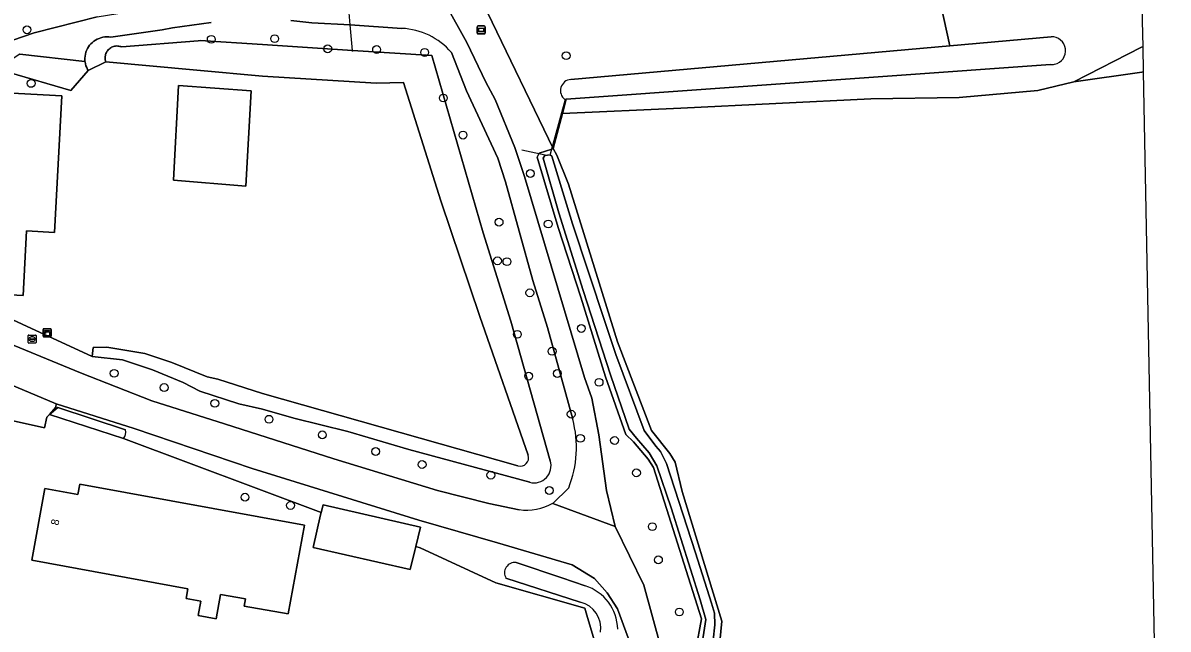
# Model space of a CAD drawing. Extents: x 163859 to 164644, y 379566 to 382155.
# Drawn here: x 164470.1 to 164613.1, y 381262.4 to 381338.2 of the extents above; entities that cross this region are included whole.
import ezdxf

# ---------------------------------------------------------------- set-up
doc = ezdxf.new("R2010")
doc.units = 0
for name, color, linetype in [('IMGEO_Boom', 7, 'Continuous'), ('IMGEO_Duiker', 7, 'Continuous'), ('IMGEO_Erf', 7, 'Continuous'), ('IMGEO_Grasland_agrarisch', 7, 'Continuous'), ('IMGEO_Grasland_overig', 7, 'Continuous'), ('IMGEO_Groenvoorziening', 7, 'Continuous'), ('IMGEO_Houtwal', 7, 'Continuous'), ('IMGEO_Kast', 7, 'Continuous'), ('IMGEO_Oever', 7, 'Continuous'), ('IMGEO_Pand', 7, 'Continuous'), ('IMGEO_Pand_nummerreeks', 7, 'Continuous'), ('IMGEO_Rijbaan_lokaal_onverhard', 7, 'Continuous'), ('IMGEO_Rijbaan_lokaal_open', 7, 'Continuous'), ('IMGEO_Rioolput', 7, 'Continuous'), ('IMGEO_Sloot', 7, 'Continuous'), ('IMGEO_Verklikker', 7, 'Continuous'), ('IMGEO_Waterloop', 7, 'Continuous')]:
    doc.layers.add(name, color=color, linetype=linetype)

msp = doc.modelspace()

# ---------------------------------------------------------------- linework, layer by layer
at = {"layer": 'IMGEO_Boom'}
for centre in [(164470.56, 381337.3), (164493.58, 381336.1), (164501.5, 381336.19), (164508.13, 381334.92), (164514.23, 381334.83), (164520.24, 381334.47), (164537.91, 381334.06), (164471.08, 381330.6), (164522.56, 381328.77), (164525.03, 381324.14), (164533.43, 381319.34), (164529.53, 381313.26), (164535.67, 381313.03), (164529.33, 381308.42), (164530.51, 381308.33), (164533.37, 381304.43), (164539.8, 381299.98), (164531.81, 381299.24), (164536.15, 381297.13), (164481.45, 381294.37), (164533.23, 381294.02), (164536.8, 381294.35), (164487.7, 381292.59), (164542.02, 381293.24), (164494.03, 381290.62), (164500.8, 381288.63), (164538.54, 381289.27), (164507.46, 381286.68), (164539.69, 381286.24), (164543.95, 381285.98), (164514.11, 381284.6), (164519.92, 381282.97), (164528.5, 381281.65), (164546.69, 381281.93), (164535.8, 381279.73), (164497.8, 381278.89), (164503.48, 381277.86), (164548.67, 381275.21), (164549.43, 381271.06), (164552.05, 381264.55)]:
    msp.add_circle(centre, 0.489, dxfattribs=at)
at = {"layer": 'IMGEO_Duiker'}
for points in [[(164511.24, 381334.6), (164511.23, 381334.72), (164510.95, 381337.93), (164510.59, 381341.96), (164510.51, 381342.79), (164510.45, 381343.54), (164510.38, 381344.3)], [(164535.97, 381321.79), (164537.82, 381328.65)], [(164535.29, 381321.62), (164532.37, 381322.25)]]:
    msp.add_lwpolyline(points, dxfattribs=at)
at = {"layer": 'IMGEO_Erf'}
for points in [[(164533.16, 381284.14), (164527.11, 381301.46), (164522.24, 381315.93), (164517.58, 381330.72), (164514.17, 381330.64), (164500, 381331.52), (164491.77, 381332.26), (164480.42, 381333.29), (164478.19, 381332.23), (164476.06, 381329.71), (164468.34, 381331.96)], [(164462.53, 381329.73), (164474.92, 381329.06), (164473.99, 381311.97), (164470.51, 381312.16), (164470.07, 381304.08), (164461.17, 381304.57), (164478.7, 381296.48), (164478.84, 381297.61), (164480.52, 381297.66), (164485.3, 381296.85), (164488.67, 381295.71), (164493.06, 381293.94), (164494.41, 381293.63), (164500, 381291.84), (164531.88, 381282.81)], [(164540.48, 381264.15), (164540.22, 381265.04), (164529.13, 381268.21), (164519.66, 381272.56), (164519.13, 381272.75), (164519.01, 381272.24), (164518.44, 381269.85), (164506.29, 381272.62), (164507.24, 381276.67), (164507.32, 381276.99), (164482.61, 381286.22), (164473.39, 381289.21), (164473.36, 381289.22), (164473.05, 381288.89), (164472.77, 381287.54), (164467.73, 381288.69), (164467.97, 381290.2), (164467.94, 381291.26), (164465.61, 381292.14), (164452.98, 381297.38), (164446.5, 381299.3), (164441.21, 381300.01)], [(164466.17, 381201.68), (164476.78, 381197.2), (164491.42, 381190.96), (164495.42, 381189.33), (164510.56, 381183.16), (164532.99, 381173.22), (164546.62, 381166.36), (164547, 381170.23), (164549.74, 381175.85), (164563.17, 381203.39), (164563.87, 381204.82), (164557.87, 381208.62), (164557.76, 381208.98), (164555.31, 381209.02), (164551.74, 381210.06), (164552.9, 381214.15), (164556.3, 381213.51), (164555.39, 381215.78), (164555.19, 381216.36), (164547.24, 381240.23), (164545.64, 381243.44), (164546.57, 381243.66), (164544.69, 381250), (164540.48, 381264.15)]]:
    msp.add_lwpolyline(points, dxfattribs=at)
for points in [[(164497.92, 381317.77), (164488.86, 381318.51), (164489.5, 381330.35), (164498.57, 381329.66)], [(164491.96, 381264.09), (164492.29, 381265.89), (164490.43, 381266.23), (164490.66, 381267.46), (164471.17, 381271.03), (164472.81, 381279.98), (164476.92, 381279.23), (164477.16, 381280.54), (164505.21, 381275.41), (164503.18, 381264.31), (164497.68, 381265.27), (164497.85, 381266.18), (164494.75, 381266.75), (164494.19, 381263.68)]]:
    msp.add_lwpolyline(points, close=True, dxfattribs=at)
msp.add_arc((164532.17, 381283.81), 1.04, 254.0114, 18.1006, dxfattribs=at)
at = {"layer": 'IMGEO_Grasland_agrarisch'}
msp.add_lwpolyline([(164611.6, 381250), (164610.02, 381332.03), (164609.81, 381332), (164601.31, 381330.81), (164596.82, 381329.72), (164586.98, 381328.83), (164575.98, 381328.66), (164552.22, 381327.5), (164537.45, 381326.82), (164536.3, 381322.47), (164536.75, 381321.62), (164538.21, 381318.01), (164544.33, 381298.3), (164548.58, 381287.22), (164550.85, 381284.34), (164551.54, 381283.27), (164552.4, 381279.61), (164557.37, 381263.39), (164556.93, 381259.1)], dxfattribs=at)
at = {"layer": 'IMGEO_Grasland_overig'}
for points in [[(164564.61, 381431.54), (164564.53, 381431.95), (164564.32, 381432.7), (164557.45, 381431.4), (164557.52, 381431.13), (164559.87, 381421.34), (164564.53, 381407.1), (164565.06, 381406.39), (164575.05, 381361.38), (164578.44, 381343.7), (164564.56, 381341.91), (164528.1, 381339.46), (164536.3, 381322.47), (164537.45, 381326.82), (164537.92, 381328.61), (164537.74, 381328.6)], [(164538.48, 381331.09), (164585.83, 381335.31), (164584.71, 381340.41)]]:
    msp.add_lwpolyline(points, dxfattribs=at)
for points in [[(164468.34, 381331.96), (164476.06, 381329.71), (164478.19, 381332.23), (164478.12, 381332.35), (164478.02, 381332.57), (164477.93, 381332.8), (164477.86, 381333.04), (164477.82, 381333.28), (164477.81, 381333.35), (164469.66, 381334.24), (164465.28, 381331.44)], [(164610.02, 381332.03), (164609.96, 381335.18), (164609.75, 381335.12), (164601.31, 381330.81), (164609.81, 381332)]]:
    msp.add_lwpolyline(points, close=True, dxfattribs=at)
msp.add_arc((164538.6, 381329.7), 1.4, 94.7737, 232.3379, dxfattribs=at)
at = {"layer": 'IMGEO_Groenvoorziening'}
for points in [[(164519.97, 381345.71), (164525.51, 381335.7), (164527.86, 381330.74), (164529.04, 381328.58), (164531.51, 381322.61), (164532.72, 381318.95), (164540.2, 381293.84), (164541.11, 381291.26), (164542, 381286.69), (164542.93, 381279.72), (164544.02, 381275.23), (164547.6, 381267.91), (164550.85, 381256.01)], [(164464.88, 381334.66), (164471.46, 381336.92), (164479.32, 381338.91), (164487.33, 381340.19), (164500, 381340.97), (164507.73, 381341.45), (164508.25, 381341.43), (164508.78, 381341.47), (164509.29, 381341.54), (164509.8, 381341.67), (164510.3, 381341.84), (164510.59, 381341.96)], [(164554.09, 381259.85), (164554.8, 381263.71), (164548.81, 381282.59), (164548.13, 381283.64), (164546.33, 381285.83), (164545.36, 381286.71), (164542.82, 381293.93), (164539.75, 381303.88), (164536.91, 381312.6), (164534.29, 381321.38), (164534.55, 381321.89), (164536.11, 381322.4), (164536.3, 381322.47), (164528.1, 381339.46)], [(164493.57, 381338.22), (164488.73, 381337.54), (164487.43, 381337.28), (164481.02, 381336.37), (164480.78, 381336.4), (164480.53, 381336.41), (164480.28, 381336.4), (164480.04, 381336.36), (164479.8, 381336.3), (164479.57, 381336.23), (164479.34, 381336.13), (164479.12, 381336.01), (164478.92, 381335.87), (164478.73, 381335.72), (164478.55, 381335.55), (164478.39, 381335.36), (164478.25, 381335.16), (164478.12, 381334.95), (164478.01, 381334.73), (164477.93, 381334.5), (164477.86, 381334.26), (164477.82, 381334.02), (164477.8, 381333.77), (164477.8, 381333.53), (164477.81, 381333.35), (164477.82, 381333.28), (164477.86, 381333.04), (164477.93, 381332.8), (164478.02, 381332.57), (164478.12, 381332.35), (164478.19, 381332.23), (164480.42, 381333.29), (164480.41, 381333.3), (164480.38, 381333.43), (164480.35, 381333.56), (164480.33, 381333.69), (164480.33, 381333.82), (164480.34, 381333.95), (164480.36, 381334.09), (164480.39, 381334.21), (164480.43, 381334.34), (164480.49, 381334.46), (164480.55, 381334.58), (164480.63, 381334.69), (164480.71, 381334.79), (164480.81, 381334.88), (164480.91, 381334.97), (164481.02, 381335.04), (164481.13, 381335.11), (164481.25, 381335.17), (164481.38, 381335.21), (164481.5, 381335.24), (164481.64, 381335.27), (164481.77, 381335.28), (164481.9, 381335.27), (164482.03, 381335.26), (164482.16, 381335.23), (164482.29, 381335.2), (164482.41, 381335.15), (164491.96, 381335.93), (164492.21, 381335.95), (164500, 381335.46), (164511.23, 381334.72), (164521.15, 381334.07), (164527.55, 381311.94), (164530.99, 381300.89), (164535.92, 381283.45)], [(164517.38, 381337.48), (164510.95, 381337.93), (164506.16, 381338.16), (164503.52, 381338.44)], [(164535.57, 381300.09), (164533.74, 381305.97), (164530.34, 381318.29), (164529.38, 381321.24), (164525.48, 381329.66), (164523.57, 381334.47)], [(164440.44, 381310.16), (164443.05, 381308.08), (164444.17, 381307.54), (164445.36, 381306.97), (164450.93, 381304.74), (164466.11, 381299), (164477.26, 381294.42), (164486.16, 381290.94), (164495.22, 381288.05), (164508.89, 381283.7), (164521.82, 381279.71), (164528.23, 381278.11), (164532.04, 381277.33)], [(164533.35, 381280.76), (164518.25, 381284.86), (164510.63, 381287.11), (164503.88, 381288.77), (164500, 381289.89), (164497.01, 381290.56), (164492.17, 381292.13), (164490.07, 381293.22), (164486.26, 381294.81), (164482.51, 381296.05), (164478.7, 381296.48), (164461.17, 381304.57)], [(164538.73, 381288.63), (164535.57, 381300.09)], [(164549.08, 381248.8), (164545.66, 381261.33), (164544.34, 381264.96), (164543.02, 381266.93), (164541.43, 381268.75), (164538.66, 381270.43), (164529.34, 381273.18), (164519.5, 381276.01), (164498.67, 381282.49), (164483.96, 381287.46), (164474.21, 381290.55), (164474.18, 381290.13), (164473.36, 381289.22), (164473.39, 381289.21), (164474.43, 381290.12), (164482.88, 381287.29)], [(164482.61, 381286.22), (164507.32, 381276.99), (164507.54, 381277.94), (164519.7, 381275.16), (164519.13, 381272.75), (164519.66, 381272.56), (164529.13, 381268.21), (164540.22, 381265.04), (164540.48, 381264.15), (164544.69, 381250)], [(164536.24, 381278.12), (164538.24, 381280.07)], [(164531.65, 381270.74), (164537.38, 381268.81), (164540.3, 381267.83)], [(164539.67, 381265.79), (164530.39, 381268.77)]]:
    msp.add_lwpolyline(points, dxfattribs=at)
for centre, radius, start, end in [((164517, 381328.82), 8.66, 40.6544, 87.4808), ((164525.53, 381285.1), 13.66, 338.4212, 14.9848), ((164481.86, 381286.98), 1.06, 314.7286, 17.3501), ((164533.9, 381282.8), 2.12, 254.882, 17.7986), ((164532.99, 381283.82), 6.55, 261.6407, 299.7286), ((164531.52, 381269.44), 1.31, 84.1793, 210.6611), ((164538.44, 381262.22), 5.91, 1.8256, 71.6465), ((164538.88, 381262.54), 3.34, 350.9797, 76.274)]:
    msp.add_arc(centre, radius, start, end, dxfattribs=at)
at = {"layer": 'IMGEO_Houtwal'}
for points in [[(164609.96, 381335.18), (164609.89, 381338.43), (164609.82, 381342.43), (164609.61, 381342.42), (164584.71, 381340.41), (164585.83, 381335.31), (164598.48, 381336.44)], [(164598.41, 381332.95), (164537.92, 381328.61), (164537.45, 381326.82), (164552.22, 381327.5), (164575.98, 381328.66), (164586.98, 381328.83), (164596.82, 381329.72), (164601.31, 381330.81), (164609.75, 381335.12), (164609.96, 381335.18)]]:
    msp.add_lwpolyline(points, dxfattribs=at)
for centre, radius, start, end in [((164598.54, 381334.69), 1.74, 282.5456, 91.8394), ((164598.54, 381334.68), 1.73, 265.8131, 282.5843)]:
    msp.add_arc(centre, radius, start, end, dxfattribs=at)
at = {"layer": 'IMGEO_Kast'}
for p, q in [((164472.65, 381299.93), (164473.49, 381299.93)), ((164473.49, 381299.93), (164472.65, 381299.93)), ((164472.58, 381299.01), (164472.58, 381299.85)), ((164472.58, 381299.85), (164472.58, 381299.01)), ((164473.5, 381298.93), (164472.66, 381298.93)), ((164472.66, 381298.93), (164473.5, 381298.93)), ((164473.58, 381299.86), (164473.58, 381299.02)), ((164473.58, 381299.02), (164473.58, 381299.86))]:
    msp.add_line(p, q, dxfattribs=at)
for points in [[(164472.77, 381299.72), (164473.37, 381299.72), (164473.37, 381299.64), (164472.77, 381299.64), (164472.77, 381299.72)], [(164472.77, 381299.55), (164473.37, 381299.55), (164473.37, 381299.06), (164472.77, 381299.06), (164472.77, 381299.55)]]:
    msp.add_lwpolyline(points, dxfattribs=at)
msp.add_circle((164472.86, 381299.4), 0.0377, dxfattribs=at)
for centre, start, end in [((164472.66, 381299.86), 92.4484, 184.2845), ((164472.66, 381299.86), 92.4484, 184.2845), ((164473.5, 381299.86), 2.4484, 94.2845), ((164473.5, 381299.86), 2.4484, 94.2845), ((164472.66, 381299.01), 182.4484, 274.2845), ((164472.66, 381299.01), 182.4484, 274.2845), ((164473.5, 381299.01), 272.4484, 4.2845), ((164473.5, 381299.01), 272.4484, 4.2845)]:
    msp.add_arc(centre, 0.0779, start, end, dxfattribs=at)
at = {"layer": 'IMGEO_Oever'}
for points in [[(164556.93, 381259.1), (164557.37, 381263.39), (164552.4, 381279.61), (164551.54, 381283.27), (164550.85, 381284.34), (164548.58, 381287.22), (164544.33, 381298.3), (164538.21, 381318.01), (164536.75, 381321.62), (164536.3, 381322.47), (164536.11, 381322.4), (164534.55, 381321.89), (164534.29, 381321.38), (164536.91, 381312.6), (164539.75, 381303.88), (164542.82, 381293.93), (164545.36, 381286.71), (164546.33, 381285.83), (164548.13, 381283.64), (164548.81, 381282.59), (164554.8, 381263.71), (164554.09, 381259.85)], [(164554.72, 381259.58), (164555.36, 381263.6), (164554.64, 381266.06), (164551.02, 381277.55), (164549.24, 381282.82), (164548.29, 381284.43), (164546.7, 381286.25), (164545.77, 381287.41), (164543.46, 381294.19), (164540.05, 381304.71), (164536.99, 381314.42), (164535.04, 381321.26), (164535.23, 381321.6), (164535.89, 381321.68), (164536.1, 381321.51), (164538.72, 381313.07), (164542.72, 381300.85), (164544.11, 381296.72), (164547.64, 381287.24), (164549.11, 381285.26), (164549.69, 381284.6), (164550.45, 381283.1), (164550.93, 381281.57), (164554.05, 381271.94), (164556.06, 381265.66), (164556.44, 381264.39), (164556.47, 381262.94), (164556.08, 381259.13)]]:
    msp.add_lwpolyline(points, dxfattribs=at)
at = {"layer": 'IMGEO_Pand'}
for points in [[(164497.92, 381317.77), (164498.57, 381329.66), (164489.5, 381330.35), (164488.86, 381318.51)], [(164462.53, 381329.73), (164461.17, 381304.57), (164470.07, 381304.08), (164470.51, 381312.16), (164473.99, 381311.97), (164474.92, 381329.06)], [(164505.21, 381275.41), (164477.16, 381280.54), (164476.92, 381279.23), (164472.81, 381279.98), (164471.17, 381271.03), (164490.66, 381267.46), (164490.43, 381266.23), (164492.29, 381265.89), (164491.96, 381264.09), (164494.19, 381263.68), (164494.75, 381266.75), (164497.85, 381266.18), (164497.68, 381265.27), (164503.18, 381264.31)], [(164519.01, 381272.24), (164519.13, 381272.75), (164519.7, 381275.16), (164507.54, 381277.94), (164507.32, 381276.99), (164507.24, 381276.67), (164506.29, 381272.62), (164518.44, 381269.85)]]:
    msp.add_lwpolyline(points, close=True, dxfattribs=at)
at = {"layer": 'IMGEO_Rijbaan_lokaal_onverhard'}
for points in [[(164538.24, 381280.07), (164536.24, 381278.12), (164544.02, 381275.23), (164542.93, 381279.72), (164542, 381286.69), (164541.11, 381291.26), (164540.2, 381293.84), (164532.72, 381318.95), (164531.51, 381322.61), (164529.04, 381328.58), (164527.86, 381330.74), (164525.51, 381335.7), (164519.97, 381345.71)], [(164479.32, 381338.91), (164471.46, 381336.92), (164464.88, 381334.66)], [(164469.66, 381334.24), (164477.81, 381333.35), (164477.8, 381333.53), (164477.8, 381333.77), (164477.82, 381334.02), (164477.86, 381334.26), (164477.93, 381334.5), (164478.01, 381334.73), (164478.12, 381334.95), (164478.25, 381335.16), (164478.39, 381335.36), (164478.55, 381335.55), (164478.73, 381335.72), (164478.92, 381335.87), (164479.12, 381336.01), (164479.34, 381336.13), (164479.57, 381336.23), (164479.8, 381336.3), (164480.04, 381336.36), (164480.28, 381336.4), (164480.53, 381336.41), (164480.78, 381336.4), (164481.02, 381336.37), (164487.43, 381337.28), (164488.73, 381337.54), (164493.57, 381338.22)], [(164503.52, 381338.44), (164506.16, 381338.16), (164510.95, 381337.93), (164517.38, 381337.48)], [(164523.57, 381334.47), (164525.48, 381329.66), (164529.38, 381321.24), (164530.34, 381318.29), (164533.74, 381305.97), (164535.57, 381300.09), (164538.73, 381288.63)], [(164532.04, 381277.33), (164528.23, 381278.11), (164521.82, 381279.71), (164508.89, 381283.7), (164495.22, 381288.05), (164486.16, 381290.94), (164477.26, 381294.42), (164466.11, 381299)], [(164468.37, 381293.01), (164474.21, 381290.55), (164483.96, 381287.46), (164498.67, 381282.49), (164519.5, 381276.01), (164529.34, 381273.18), (164538.66, 381270.43), (164541.43, 381268.75), (164543.02, 381266.93), (164544.34, 381264.96), (164545.66, 381261.33)], [(164613.09, 381172.4), (164610.08, 381176.78), (164599.24, 381192.03), (164598.13, 381193.31), (164597.11, 381194.38), (164595.79, 381195.61), (164593, 381197.74), (164590.86, 381199.36), (164586.65, 381201.83), (164584.36, 381202.3), (164579.11, 381204.6), (164574.56, 381207.73), (164570.59, 381210.11), (164567.68, 381212.22), (164565.32, 381215.07), (164562.87, 381219.96), (164558.43, 381230.39), (164555.47, 381238.84), (164553.72, 381244.89), (164550.85, 381256.01), (164547.6, 381267.91), (164544.02, 381275.23), (164536.24, 381278.12)]]:
    msp.add_lwpolyline(points, dxfattribs=at)
for centre, radius, start, end in [((164517, 381328.82), 8.66, 40.6544, 87.4808), ((164525.53, 381285.1), 13.66, 338.4212, 14.9848), ((164532.99, 381283.82), 6.55, 261.6407, 299.7286)]:
    msp.add_arc(centre, radius, start, end, dxfattribs=at)
at = {"layer": 'IMGEO_Rijbaan_lokaal_open'}
msp.add_lwpolyline([(164474.21, 381290.55), (164468.37, 381293.01), (164467.86, 381292.65), (164467.84, 381292.68), (164467.72, 381292.32), (164467.94, 381291.52), (164467.94, 381291.26), (164467.97, 381290.2), (164467.73, 381288.69), (164472.77, 381287.54), (164473.05, 381288.89), (164473.36, 381289.22), (164474.18, 381290.13)], close=True, dxfattribs=at)
at = {"layer": 'IMGEO_Rioolput'}
for p, q in [((164470.71, 381298.23), (164470.71, 381299.08)), ((164470.78, 381299.15), (164471.63, 381299.15)), ((164470.96, 381298.65), (164470.96, 381298.66)), ((164471.4, 381298.61), (164471, 381298.61)), ((164471.01, 381298.7), (164471.4, 381298.7)), ((164471.19, 381298.93), (164471.22, 381298.93)), ((164471.45, 381298.66), (164471.45, 381298.65)), ((164471.71, 381299.08), (164471.71, 381298.23)), ((164471.63, 381298.15), (164470.78, 381298.15)), ((164471.22, 381298.37), (164471.19, 381298.37))]:
    msp.add_line(p, q, dxfattribs=at)
for points in [[(164470.71, 381298.23), (164470.71, 381299.08)], [(164470.78, 381299.15), (164471.63, 381299.15)], [(164471.71, 381299.08), (164471.71, 381298.23)], [(164471.63, 381298.15), (164470.78, 381298.15)]]:
    msp.add_lwpolyline(points, dxfattribs=at)
for centre, radius, start, end in [((164470.78, 381299.08), 0.0765, 91.552, 178.448), ((164470.78, 381299.08), 0.0765, 91.552, 178.448), ((164471, 381298.66), 0.0403, 85.8775, 175.7526), ((164471, 381298.65), 0.0366, 178.938, 274.7102), ((164471.41, 381298.66), 0.0386, 1.7309, 96.639), ((164471.41, 381298.65), 0.043, 264.8664, 352.4533), ((164471.63, 381299.08), 0.0765, 1.552, 88.448), ((164471.63, 381299.08), 0.0765, 1.552, 88.448), ((164470.78, 381298.23), 0.0765, 181.552, 268.448), ((164470.78, 381298.23), 0.0765, 181.552, 268.448), ((164471.63, 381298.23), 0.0765, 271.552, 358.448), ((164471.63, 381298.23), 0.0765, 271.552, 358.448)]:
    msp.add_arc(centre, radius, start, end, dxfattribs=at)
for centre, major_axis, ratio, start_param, end_param in [((164471.19, 381298.65), (-0.387, 0.002), 0.722429, 4.712389, 7.853982), ((164471.22, 381298.65), (-0.39, 0.002), 0.717154, 1.570796, 4.712389)]:
    msp.add_ellipse(centre, major_axis=major_axis, ratio=ratio, start_param=start_param, end_param=end_param, dxfattribs=at)
at = {"layer": 'IMGEO_Sloot'}
msp.add_lwpolyline([(164556.08, 381259.13), (164556.47, 381262.94), (164556.44, 381264.39), (164556.06, 381265.66), (164554.05, 381271.94), (164550.93, 381281.57), (164550.45, 381283.1), (164549.69, 381284.6), (164549.11, 381285.26), (164547.64, 381287.24), (164544.11, 381296.72), (164542.72, 381300.85), (164538.72, 381313.07), (164536.1, 381321.51), (164535.89, 381321.68), (164535.23, 381321.6), (164535.04, 381321.26), (164536.99, 381314.42), (164540.05, 381304.71), (164543.46, 381294.19), (164545.77, 381287.41), (164546.7, 381286.25), (164548.29, 381284.43), (164549.24, 381282.82), (164551.02, 381277.55), (164554.64, 381266.06), (164555.36, 381263.6), (164554.72, 381259.58)], dxfattribs=at)
at = {"layer": 'IMGEO_Verklikker'}
for p, q in [((164526.79, 381336.88), (164526.79, 381337.68)), ((164526.79, 381337.68), (164526.79, 381336.88)), ((164526.89, 381337.78), (164527.68, 381337.78)), ((164527.68, 381337.78), (164526.89, 381337.78)), ((164527.78, 381337.68), (164527.78, 381336.88)), ((164527.78, 381336.88), (164527.78, 381337.68)), ((164527.68, 381336.78), (164526.89, 381336.78)), ((164526.89, 381336.78), (164527.68, 381336.78))]:
    msp.add_line(p, q, dxfattribs=at)
for points in [[(164526.89, 381337.51), (164527.68, 381337.51), (164527.68, 381337.05), (164526.89, 381337.05), (164526.89, 381337.51)], [(164526.95, 381337.45), (164526.95, 381337.11), (164527.61, 381337.11), (164527.61, 381337.45), (164526.95, 381337.45)]]:
    msp.add_lwpolyline(points, dxfattribs=at)
for centre, start, end in [((164526.89, 381337.68), 90, 180), ((164526.89, 381337.68), 90, 180), ((164527.68, 381337.68), 0, 90), ((164527.68, 381337.68), 360, 90), ((164526.89, 381336.88), 180, 270), ((164526.89, 381336.88), 180, 270), ((164527.68, 381336.88), 270, 0), ((164527.68, 381336.88), 270, 0)]:
    msp.add_arc(centre, 0.1, start, end, dxfattribs=at)
at = {"layer": 'IMGEO_Waterloop'}
for points in [[(164535.92, 381283.45), (164530.99, 381300.89), (164527.55, 381311.94), (164521.15, 381334.07), (164511.23, 381334.72), (164500, 381335.46), (164492.21, 381335.95), (164491.96, 381335.93), (164482.41, 381335.15), (164482.29, 381335.2), (164482.16, 381335.23), (164482.03, 381335.26), (164481.9, 381335.27), (164481.77, 381335.28), (164481.64, 381335.27), (164481.5, 381335.24), (164481.38, 381335.21), (164481.25, 381335.17), (164481.13, 381335.11), (164481.02, 381335.04), (164480.91, 381334.97), (164480.81, 381334.88), (164480.71, 381334.79), (164480.63, 381334.69), (164480.55, 381334.58), (164480.49, 381334.46), (164480.43, 381334.34), (164480.39, 381334.21), (164480.36, 381334.09), (164480.34, 381333.95), (164480.33, 381333.82), (164480.33, 381333.69), (164480.35, 381333.56), (164480.38, 381333.43), (164480.41, 381333.3), (164480.42, 381333.29), (164491.77, 381332.26), (164500, 381331.52), (164514.17, 381330.64), (164517.58, 381330.72), (164522.24, 381315.93), (164527.11, 381301.46), (164533.16, 381284.14)], [(164598.48, 381336.44), (164585.83, 381335.31)], [(164585.83, 381335.31), (164538.48, 381331.09)], [(164537.74, 381328.6), (164537.92, 381328.61), (164598.41, 381332.95)], [(164531.88, 381282.81), (164500, 381291.84), (164494.41, 381293.63), (164493.06, 381293.94), (164488.67, 381295.71), (164485.3, 381296.85), (164480.52, 381297.66), (164478.84, 381297.61), (164478.7, 381296.48), (164482.51, 381296.05), (164486.26, 381294.81), (164490.07, 381293.22), (164492.17, 381292.13), (164497.01, 381290.56), (164500, 381289.89), (164503.88, 381288.77), (164510.63, 381287.11), (164518.25, 381284.86), (164533.35, 381280.76)], [(164482.88, 381287.29), (164474.43, 381290.12), (164473.39, 381289.21), (164482.61, 381286.22)], [(164537.38, 381268.81), (164531.65, 381270.74)], [(164530.39, 381268.77), (164539.67, 381265.79)], [(164540.3, 381267.83), (164537.38, 381268.81)]]:
    msp.add_lwpolyline(points, dxfattribs=at)
for centre, radius, start, end in [((164598.54, 381334.69), 1.74, 282.5456, 91.8394), ((164598.54, 381334.68), 1.73, 265.8131, 282.5843), ((164538.6, 381329.7), 1.4, 94.7737, 232.3379), ((164481.86, 381286.98), 1.06, 314.7286, 17.3501), ((164532.17, 381283.81), 1.04, 254.0114, 18.1006), ((164533.9, 381282.8), 2.12, 254.882, 17.7986), ((164531.52, 381269.44), 1.31, 84.1793, 210.6611), ((164538.44, 381262.22), 5.91, 1.8256, 71.6465), ((164538.88, 381262.54), 3.34, 350.9797, 76.274)]:
    msp.add_arc(centre, radius, start, end, dxfattribs=at)

# ---------------------------------------------------------------- texts
at = {"layer": 'IMGEO_Pand_nummerreeks'}
msp.add_text('8', height=1, rotation=79.6297, dxfattribs=at).set_placement((164474.5, 381275.32))

doc.saveas('drawing.dxf')
